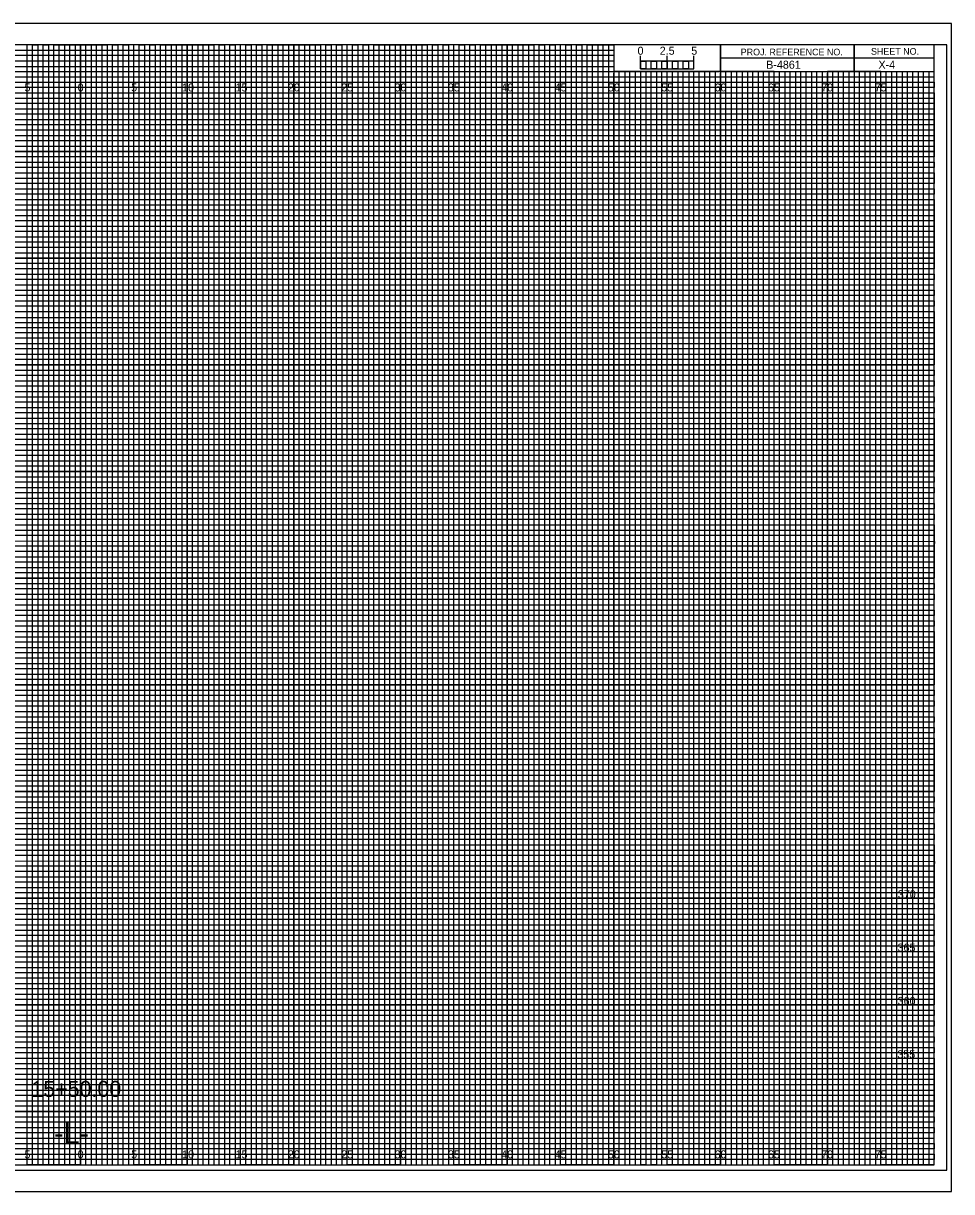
# Model space of a CAD drawing. Extents: x -7 to 266, y -5 to 437.
# Drawn here: x 74.6 to 161.7, y 327.5 to 437 of the extents above; entities that cross this region are included whole.
import ezdxf

# ---------------------------------------------------------------- set-up
doc = ezdxf.new("R2010")
doc.units = 0
for name, color, linetype in [('Exist XS Center Line Elevation Label', 7, 'Continuous'), ('Exist XS Ground Line', 7, 'Continuous'), ('Prop XS Dump Level', 7, 'Continuous'), ('Prop XS EOT Tick Mark', 7, 'Continuous'), ('Prop XS Finish Grade', 7, 'Continuous'), ('Prop XS Finish Grade Concrete', 7, 'Continuous'), ('Prop XS Finish Grade Earthwork', 7, 'Continuous'), ('Prop XS Finish Grade Pavement', 7, 'Continuous'), ('Prop XS Geopak Shape', 7, 'Continuous'), ('Prop XS Hydro Elevations', 7, 'Continuous'), ('Prop XS Pvmt Edge Slope', 7, 'Continuous'), ('Prop XS SE Text', 7, 'Continuous'), ('Prop XS Side Slope Text', 7, 'Continuous'), ('Prop XS SS Elevation Text', 7, 'Continuous'), ('Prop XS Subgrade Earthwork', 7, 'Continuous'), ('Prop XSC Text', 7, 'Continuous'), ('Typical Guardrail CELL', 7, 'Continuous')]:
    doc.layers.add(name, color=color, linetype=linetype)

msp = doc.modelspace()

# ---------------------------------------------------------------- linework, layer by layer
at = {"layer": 'Exist XS Center Line Elevation Label'}
for points in [[(72.5, 330), (77.5, 330), (77.5, 435), (82.5, 435), (82.5, 330), (87.5, 330), (87.5, 435), (92.5, 435), (92.5, 330), (97.5, 330), (97.5, 435), (102.5, 435), (102.5, 330), (107.5, 330), (107.5, 435), (112.5, 435), (112.5, 330), (117.5, 330), (117.5, 435), (122.5, 435), (122.5, 330), (127.5, 330), (127.5, 435), (129.97, 435), (130, 435), (130, 432.5), (132.5, 432.5), (132.5, 330), (137.5, 330), (137.5, 432.5), (142.5, 432.5), (142.5, 330), (147.5, 330), (147.5, 432.5), (152.5, 432.5), (152.5, 330), (157.5, 330), (157.5, 432.5)], [(0, 432.5), (137.5, 432.5)], [(0, 422.5), (160, 422.5), (160, 427.5), (0, 427.5)], [(0, 412.5), (160, 412.5), (160, 417.5), (0, 417.5)], [(0, 402.5), (160, 402.5), (160, 407.5), (0, 407.5)], [(0, 392.5), (160, 392.5), (160, 397.5), (0, 397.5)], [(0, 382.5), (160, 382.5), (160, 387.5), (0, 387.5)], [(0, 372.5), (160, 372.5), (160, 377.5), (0, 377.5)], [(0, 362.5), (160, 362.5), (160, 367.5), (0, 367.5)], [(0, 352.5), (160, 352.5), (160, 357.5), (0, 357.5)], [(0, 342.5), (160, 342.5), (160, 347.5), (0, 347.5)], [(0, 332.5), (160, 332.5), (160, 337.5), (0, 337.5)]]:
    msp.add_lwpolyline(points, dxfattribs=at)
at = {"layer": 'Exist XS Ground Line'}
for p, q in [((75, 435), (70, 435)), ((75, 330), (75, 435)), ((85, 435), (80, 435)), ((80, 435), (80, 330)), ((85, 330), (85, 435)), ((95, 435), (90, 435)), ((90, 435), (90, 330)), ((95, 330), (95, 435)), ((105, 435), (100, 435)), ((100, 435), (100, 330)), ((105, 330), (105, 435)), ((115, 435), (110, 435)), ((110, 435), (110, 330)), ((115, 330), (115, 435)), ((125, 435), (120, 435)), ((120, 435), (120, 330)), ((125, 330), (125, 435)), ((130, 435), (130, 330)), ((135, 330), (135, 432.5)), ((145, 432.5), (140, 432.5)), ((140, 432.5), (140, 330)), ((145, 330), (145, 432.5)), ((155, 432.5), (150, 432.5)), ((150, 432.5), (150, 330)), ((155, 330), (155, 432.5)), ((80, 330), (75, 330)), ((90, 330), (85, 330)), ((100, 330), (95, 330)), ((110, 330), (105, 330)), ((120, 330), (115, 330)), ((130, 330), (125, 330)), ((140, 330), (135, 330)), ((150, 330), (145, 330)), ((160, 330), (155, 330)), ((160, 330), (160, 330))]:
    msp.add_line(p, q, dxfattribs=at)
for points in [[(0, 430), (160, 430), (160, 425), (0, 425)], [(0, 420), (160, 420), (160, 415), (0, 415)], [(0, 410), (160, 410), (160, 405), (0, 405)], [(0, 400), (160, 400), (160, 395), (0, 395)], [(0, 390), (160, 390), (160, 385), (0, 385)], [(0, 380), (160, 380), (160, 375), (0, 375)], [(0, 370), (160, 370), (160, 365), (0, 365)], [(0, 360), (160, 360), (160, 355), (0, 355)], [(0, 350), (160, 350), (160, 345), (0, 345)], [(0, 340), (160, 340), (160, 335), (0, 335)]]:
    msp.add_lwpolyline(points, dxfattribs=at)
at = {"layer": 'Prop XS Finish Grade'}
for p, q in [((75, 330), (75, 435)), ((80, 330), (80, 435)), ((85, 330), (85, 435)), ((90, 330), (90, 435)), ((95, 330), (95, 435)), ((100, 330), (100, 435)), ((105, 330), (105, 435)), ((110, 330), (110, 435)), ((115, 330), (115, 435)), ((120, 330), (120, 435)), ((125, 330), (125, 435)), ((130, 330), (130, 432.34)), ((135, 330), (135, 432.34)), ((140, 330), (140, 432.34)), ((145, 330), (145, 432.34)), ((150, 330), (150, 432.34)), ((155, 330), (155, 432.34)), ((0, 430), (160, 430)), ((0, 425), (160, 425)), ((0, 420), (160, 420)), ((0, 415), (160, 415)), ((0, 410), (160, 410)), ((0, 405), (160, 405)), ((0, 400), (160, 400)), ((0, 395), (160, 395)), ((0, 390), (160, 390)), ((0, 385), (160, 385)), ((0, 380), (160, 380)), ((0, 375), (160, 375)), ((0, 370), (160, 370)), ((0, 365), (160, 365)), ((0, 360), (160, 360)), ((0, 355), (160, 355)), ((0, 350), (160, 350)), ((0, 345), (160, 345)), ((0, 340), (160, 340)), ((0, 335), (160, 335))]:
    msp.add_line(p, q, dxfattribs=at)
at = {"layer": 'Prop XS Finish Grade Earthwork'}
msp.add_lwpolyline([(-6.7, 327.5), (161.65, 327.5), (161.65, 437), (-6.7, 437)], close=True, dxfattribs=at)
at = {"layer": 'Prop XS Hydro Elevations'}
for p, q in [((152.5, 435), (152.5, 432.5)), ((152.5, 432.5), (152.5, 435)), ((160, 433.75), (140, 433.75)), ((140, 433.75), (140, 432.5)), ((140, 432.5), (160, 432.5))]:
    msp.add_line(p, q, dxfattribs=at)
for points in [[(160, 435), (0, 435), (0, 330), (160, 330)], [(140, 435), (130, 435), (130, 432.51), (140, 432.51)], [(160, 435), (140, 435), (140, 432.5), (160, 432.5)]]:
    msp.add_lwpolyline(points, close=True, dxfattribs=at)
at = {"layer": 'Prop XS Pvmt Edge Slope'}
msp.add_lwpolyline([(-5.4, 329.5), (161.2, 329.5), (161.2, 435), (-5.4, 435)], close=True, dxfattribs=at)
at = {"layer": 'Prop XS SE Text'}
for p, q in [((0, 434.5), (130, 434.5)), ((130, 433.99), (0, 433.99)), ((130, 434.5), (130, 433.99)), ((0, 433.5), (130, 433.5)), ((130, 432.94), (0, 432.94)), ((130, 433.5), (130, 432.94)), ((0, 432), (160, 432))]:
    msp.add_line(p, q, dxfattribs=at)
for points in [[(0, 431.5), (135, 431.5), (160, 431.5), (160, 431), (0, 431)], [(0, 430.5), (160, 430.5), (160, 429.5), (0, 429.5)], [(0, 429), (160, 429), (160, 428.5), (0, 428.49)], [(0, 428), (160, 428), (160, 427), (0, 427)], [(0, 426.5), (160, 426.5), (160, 426), (0, 426)], [(0, 425.5), (160, 425.5), (160, 424.5), (0, 424.5)], [(0, 424), (160, 424), (160, 423.5), (0, 423.5)], [(0, 423), (160, 423), (160, 422), (0, 422)], [(0, 421.5), (160, 421.5), (160, 421), (0, 421)], [(0, 420.5), (160, 420.5), (160, 419.5), (0, 419.5)], [(0, 419), (160, 419), (160, 418.5), (0, 418.5)], [(0, 418), (160, 418), (160, 416.98), (160, 416.5), (160, 416), (0, 416)], [(0, 417), (160, 417), (160, 416.5), (0, 416.5)], [(0, 415.5), (160, 415.5), (160, 414.5), (0, 414.51)], [(0, 414.51), (160, 414.5), (160, 414), (0, 414)], [(0, 413.5), (160, 413.5), (160, 413), (0, 413)], [(0, 412), (160, 412), (160, 411.5), (0, 411.5)], [(0, 411), (160, 411), (160, 410.5), (0, 410.5)], [(-0.04, 409.44), (160, 409.44), (160, 408.94), (-0.04, 408.94)], [(0, 408.5), (160, 408.5), (160, 408), (0, 408)], [(0, 407), (160, 407), (160, 406.5), (0, 406.5)], [(0, 406), (160, 406), (160, 405.5), (0, 405.5)], [(0, 404.5), (160, 404.5), (160, 404), (0, 404)], [(0, 403.5), (160, 403.5), (160, 403), (0, 403)], [(0, 402), (160, 402), (160, 401.5), (0, 401.5)], [(0, 401), (160, 401), (160, 400.5), (0, 400.5)], [(0, 399.5), (160, 399.5), (160, 398.99), (0, 399)], [(0, 398.5), (160, 398.5), (160, 398), (0, 398)], [(0, 397), (160, 397), (160, 396.5), (0, 396.5)], [(0, 396), (160, 396), (160, 395.5), (0, 395.5)], [(0, 394.5), (160, 394.5), (160, 394), (0, 394)], [(0, 393.5), (160, 393.5), (160, 393), (0, 393)], [(0, 392), (160, 392), (160, 391.5), (0, 391.5)], [(0, 391), (160, 391), (160, 390.5), (0, 390.5)], [(0, 389.5), (160, 389.5), (160, 389), (0, 389)], [(0, 388.5), (160.03, 388.45), (160, 388), (0, 388)], [(0, 387), (160, 387), (160, 386.5), (0, 386.5)], [(0, 386), (160, 386), (160, 385.5), (0, 385.5)], [(0, 384.5), (160, 384.5), (160, 384), (0, 384)], [(0, 383.5), (160, 383.5), (160, 383), (0, 383)], [(0, 382), (160, 382), (160, 381.5), (0, 381.5)], [(0, 381), (160, 381), (160, 380.5), (0, 380.5)], [(0, 379.5), (160, 379.5), (160, 379), (0, 379)], [(0, 378.5), (160, 378.5), (160, 378), (0, 378)], [(0, 377), (160, 377), (160, 376.5), (0, 376.5)], [(0, 376), (160, 376), (160, 375.5), (0, 375.5)], [(0, 374.5), (160, 374.5), (160, 374), (0, 374)], [(0, 373.5), (160, 373.5), (160, 373), (0, 373)], [(0, 372), (160, 372), (160, 371.5), (0, 371.5)], [(0, 371), (160, 371), (160, 370.5), (0, 370.5)], [(0, 369.5), (160, 369.5), (160, 368.99), (0, 369)], [(0, 368.5), (160, 368.5), (160, 368), (0, 368)], [(0, 367), (160, 367), (160, 366.5), (0, 366.5)], [(0, 366), (160, 366), (160, 365.5), (0, 365.5)], [(0, 364.5), (160, 364.5), (160, 364), (0, 364)], [(0, 363.5), (160, 363.5), (160, 363), (0, 363)], [(0, 362), (160, 362), (160, 361.5), (0, 361.5)], [(0, 361), (160, 361), (160, 360.5), (0, 360.5)], [(0, 359.5), (160, 359.5), (160, 359), (0, 359)], [(0, 358.5), (160.03, 358.45), (160, 358), (0, 358)], [(0, 357), (160, 357), (160, 356.5), (0, 356.5)], [(0, 356), (160, 356), (160, 355.5), (0, 355.5)], [(0, 354.5), (160, 354.5), (160, 354), (0, 354)], [(0, 353.5), (160, 353.5), (160, 353), (0, 353)], [(0, 352), (160, 352), (160, 351.5), (0, 351.5)], [(0, 351), (160, 351), (160, 350.5), (0, 350.5)], [(0, 349.5), (160, 349.5), (160, 349), (0, 349)], [(0, 348.5), (160, 348.5), (160, 348), (0, 348)], [(0, 347), (160, 347), (160, 346.5), (0, 346.5)], [(0, 346), (160, 346), (160, 345.5), (0, 345.5)], [(0, 344.5), (160, 344.5), (160, 344), (0, 344)], [(0, 343.5), (160, 343.5), (160, 343), (0, 343)], [(0, 342), (160, 342), (160, 341.5), (0, 341.5)], [(0, 341), (160, 341), (160, 340.5), (0, 340.5)], [(0, 339.5), (160, 339.5), (160, 339), (0, 339)], [(0, 338.5), (160, 338.5), (160, 338), (0, 338)], [(0, 337), (160, 337), (160, 336.5), (0, 336.5)], [(0, 336), (160, 336), (160, 335.5), (0, 335.5)], [(0, 334.5), (160, 334.5), (160, 334), (0, 334)], [(0, 333.5), (160, 333.5), (160, 333), (0, 333)], [(0, 332), (160, 332), (160, 331.5), (0, 331.5)], [(0, 331), (160, 331), (160, 330.5), (0, 330.5)]]:
    msp.add_lwpolyline(points, dxfattribs=at)
at = {"layer": 'Prop XS Side Slope Text'}
for p, q in [((132.5, 432.75), (132.5, 433.95)), ((132.5, 433.45), (132.5, 433.95)), ((135, 432.75), (135, 433.95)), ((137.5, 432.75), (137.5, 433.95)), ((137.5, 433.45), (137.5, 433.95))]:
    msp.add_line(p, q, dxfattribs=at)
for points in [[(137.5, 433.45), (132.5, 433.45), (132.5, 432.75), (137.5, 432.75)], [(132.5, 433.45), (133, 433.45), (133, 432.75), (132.5, 432.75)], [(133.5, 433.45), (134, 433.45), (134, 432.75), (133.5, 432.75)], [(134.5, 433.45), (135, 433.45), (135, 432.75), (134.5, 432.75)], [(135.5, 433.45), (136, 433.45), (136, 432.75), (135.5, 432.75)], [(136.5, 433.45), (137, 433.45), (137, 432.75), (136.5, 432.75)]]:
    msp.add_lwpolyline(points, close=True, dxfattribs=at)
at = {"layer": 'Prop XS SS Elevation Text'}
for p, q in [((133.5, 432.5), (133, 432.5)), ((133, 432.5), (133, 330)), ((133.5, 330), (133.5, 432.5)), ((134.5, 432.5), (134, 432.5)), ((134, 432.5), (134, 330)), ((134.5, 330), (134.5, 432.5)), ((133, 330), (132.5, 330)), ((134, 330), (133.5, 330))]:
    msp.add_line(p, q, dxfattribs=at)
for points in [[(75, 330), (75.5, 330), (75.5, 435), (76, 435), (76, 330)], [(76, 330), (76.5, 330), (76.5, 435), (77, 435), (77, 330)], [(77.5, 330), (78, 330), (78, 435), (78.5, 435), (78.5, 330)], [(78.5, 330), (79, 330), (79, 435), (79.5, 435), (79.5, 330)], [(80, 330), (80.5, 330), (80.5, 435), (81, 435), (81, 330)], [(81, 330), (81.5, 330), (81.5, 435), (82, 435), (82, 330)], [(82.5, 330), (83, 330), (83, 435), (83.5, 435), (83.5, 330)], [(83.5, 330), (84, 330), (84, 435), (84.5, 435), (84.5, 330)], [(85, 330), (85.5, 330), (85.5, 435), (86, 435), (86, 330)], [(86, 330), (86.5, 330), (86.5, 435), (87, 435), (87, 330)], [(87.5, 330), (88, 330), (88, 435), (88.5, 435), (88.5, 330)], [(88.5, 330), (89, 330), (89, 435), (89.5, 435), (89.5, 330)], [(90, 330), (90.5, 330), (90.5, 435), (91, 435), (91, 330)], [(91, 330), (91.5, 330), (91.5, 435), (92, 435), (92, 330)], [(92.5, 330), (93, 330), (93, 435), (93.5, 435), (93.5, 330)], [(93.5, 330), (94, 330), (94, 435), (94.5, 435), (94.5, 330)], [(95, 330), (95.5, 330), (95.5, 435), (96, 435), (96, 330)], [(96, 330), (96.5, 330), (96.5, 435), (97, 435), (97, 330)], [(97.5, 330), (98, 330), (98, 435), (98.5, 435), (98.5, 330)], [(98.5, 330), (99, 330), (99, 435), (99.5, 435), (99.5, 330)], [(100, 330), (100.5, 330), (100.5, 435), (101, 435), (101, 330)], [(101, 330), (101.5, 330), (101.5, 435), (102, 435), (102, 330)], [(102.5, 330), (103, 330), (103, 435), (103.5, 435), (103.5, 330)], [(103.5, 330), (104, 330), (104, 435), (104.5, 435), (104.5, 330)], [(105, 330), (105.5, 330), (105.5, 435), (106, 435), (106, 330)], [(106, 330), (106.5, 330), (106.5, 435), (107, 435), (107, 330)], [(107.5, 330), (108, 330), (108, 435), (108.5, 435), (108.5, 330)], [(108.5, 330), (109, 330), (109, 435), (109.5, 435), (109.5, 330)], [(110, 330), (110.5, 330), (110.5, 435), (111, 435), (111, 330)], [(111, 330), (111.5, 330), (111.5, 435), (112, 435), (112, 330)], [(112.5, 330), (113, 330), (113, 435), (113.5, 435), (113.5, 330)], [(113.5, 330), (114, 330), (114, 435), (114.5, 435), (114.5, 330)], [(115, 330), (115.5, 330), (115.5, 435), (116, 435), (116, 330)], [(116, 330), (116.5, 330), (116.5, 435), (117, 435), (117, 330)], [(117.5, 330), (118, 330), (118, 435), (118.5, 435), (118.5, 330)], [(118.5, 330), (119, 330), (119, 435), (119.5, 435), (119.5, 330)], [(120, 330), (120.5, 330), (120.5, 435), (121, 435), (121, 330)], [(121, 330), (121.5, 330), (121.5, 435), (122, 435), (122, 330)], [(122.5, 330), (123, 330), (123, 435), (123.5, 435), (123.5, 330)], [(123.5, 330), (124, 330), (124, 435), (124.5, 435), (124.5, 330)], [(125, 330), (125.5, 330), (125.5, 435), (126, 435), (126, 330)], [(126, 330), (126.5, 330), (126.5, 435), (127, 435), (127, 330)], [(127.5, 330), (128, 330), (128, 435), (128.5, 435), (128.5, 330)], [(128.5, 330), (129, 330), (129, 435), (129.5, 435), (129.5, 330)], [(130, 330), (130.5, 330), (130.5, 432.5), (131.01, 432.5), (131.01, 330)], [(131, 330), (131.5, 330), (131.5, 432.5), (132, 432.5), (132, 330)], [(135, 330), (135.49, 330), (135.49, 432.5), (136, 432.5), (136, 330)], [(136, 330), (136.5, 330), (136.5, 432.5), (137.03, 432.5), (137.03, 330)], [(137.5, 330), (138, 330), (138, 432.5), (138.5, 432.5), (138.5, 330)], [(138.5, 330), (139, 330), (139, 432.5), (139.5, 432.5), (139.5, 330)], [(140, 330), (140.5, 330), (140.5, 432.5), (141, 432.5), (141, 330)], [(141, 330), (141.5, 330), (141.5, 432.5), (142, 432.5), (142, 330)], [(142.5, 330), (143, 330), (143, 432.5), (143.5, 432.5), (143.5, 330)], [(143.5, 330), (144, 330), (144, 432.5), (144.5, 432.5), (144.5, 330)], [(145, 330), (145.5, 330), (145.5, 432.5), (146, 432.5), (146, 330)], [(146, 330), (146.5, 330), (146.5, 432.5), (147, 432.5), (147, 330)], [(147.5, 330), (148, 330), (148, 432.5), (148.5, 432.5), (148.5, 330)], [(148.5, 330), (149, 330), (149, 432.5), (149.5, 432.5), (149.5, 330)], [(150, 330), (150.5, 330), (150.5, 432.5), (151, 432.5), (151, 330)], [(151, 330), (151.5, 330), (151.5, 432.5), (152, 432.5), (152, 330)], [(152.5, 330), (153, 330), (153, 432.5), (153.5, 432.5), (153.5, 330)], [(153.5, 330), (154, 330), (154, 432.5), (154.5, 432.5), (154.5, 330)], [(155, 330), (155.5, 330), (155.5, 432.5), (156, 432.5), (156, 330)], [(156, 330), (156.5, 330), (156.5, 432.5), (157, 432.5), (157, 330)], [(157.5, 330), (158, 330), (158, 432.5), (158.5, 432.5), (158.5, 330)], [(158.5, 330), (159, 330), (159, 432.5), (159.5, 432.5), (159.5, 330)]]:
    msp.add_lwpolyline(points, dxfattribs=at)
at = {"layer": 'Prop XS Subgrade Earthwork'}
for p, q in [((161.65, 437), (-6.7, 437)), ((-6.7, 327.5), (161.65, 327.5))]:
    msp.add_line(p, q, dxfattribs=at)

# ---------------------------------------------------------------- texts
at = {"layer": 'Prop XS Dump Level'}
msp.add_text('-L-', height=2, dxfattribs=at).set_placement((77.53, 332))
at = {"layer": 'Prop XS EOT Tick Mark'}
msp.add_text('X-4', height=0.75, dxfattribs=at).set_placement((154.79, 432.75))
at = {"layer": 'Prop XS Finish Grade Concrete'}
for s, p in [('370', (156.61, 355)), ('365', (156.58, 350)), ('360', (156.59, 345)), ('355', (156.56, 340))]:
    msp.add_text(s, height=0.75, dxfattribs=at).set_placement(p)
at = {"layer": 'Prop XS Finish Grade Pavement'}
msp.add_text('B-4861', height=0.75, dxfattribs=at).set_placement((144.27, 432.75))
at = {"layer": 'Prop XS Geopak Shape'}
for s, p in [('2.5', (134.29, 434.06)), ('5', (137.24, 434.06))]:
    msp.add_text(s, height=0.75, dxfattribs=at).set_placement(p)
at = {"layer": 'Prop XS Hydro Elevations'}
for s, p in [('PROJ. REFERENCE NO.', (141.88, 434)), ('SHEET NO.', (154.09, 434.06))]:
    msp.add_text(s, height=0.625, dxfattribs=at).set_placement(p)
at = {"layer": 'Prop XS Side Slope Text'}
msp.add_text('0', height=0.75, dxfattribs=at).set_placement((132.21, 434.06))
at = {"layer": 'Prop XSC Text'}
msp.add_text('15+50.00', height=1.5, dxfattribs=at).set_placement((75.39, 336.38))
at = {"layer": 'Typical Guardrail CELL'}
for s, p in [('5', (74.74, 430.62)), ('0', (79.73, 430.62)), ('0', (79.73, 430.62)), ('5', (84.74, 430.62)), ('10', (89.52, 430.62)), ('15', (94.53, 430.62)), ('20', (99.43, 430.62)), ('25', (104.44, 430.62)), ('30', (109.43, 430.62)), ('35', (114.44, 430.62)), ('40', (119.43, 430.62)), ('45', (124.44, 430.62)), ('50', (129.43, 430.62)), ('55', (134.44, 430.62)), ('60', (139.43, 430.62)), ('65', (144.44, 430.62)), ('70', (149.43, 430.62)), ('75', (154.44, 430.62)), ('5', (74.74, 330.62)), ('0', (79.73, 330.62)), ('0', (79.73, 330.62)), ('5', (84.74, 330.62)), ('10', (89.52, 330.62)), ('15', (94.53, 330.62)), ('20', (99.43, 330.62)), ('25', (104.44, 330.62)), ('30', (109.43, 330.62)), ('35', (114.44, 330.62)), ('40', (119.43, 330.62)), ('45', (124.44, 330.62)), ('50', (129.43, 330.62)), ('55', (134.44, 330.62)), ('60', (139.43, 330.62)), ('65', (144.44, 330.62)), ('70', (149.43, 330.62)), ('75', (154.44, 330.62))]:
    msp.add_text(s, height=0.75, dxfattribs=at).set_placement(p)

doc.saveas('drawing.dxf')
